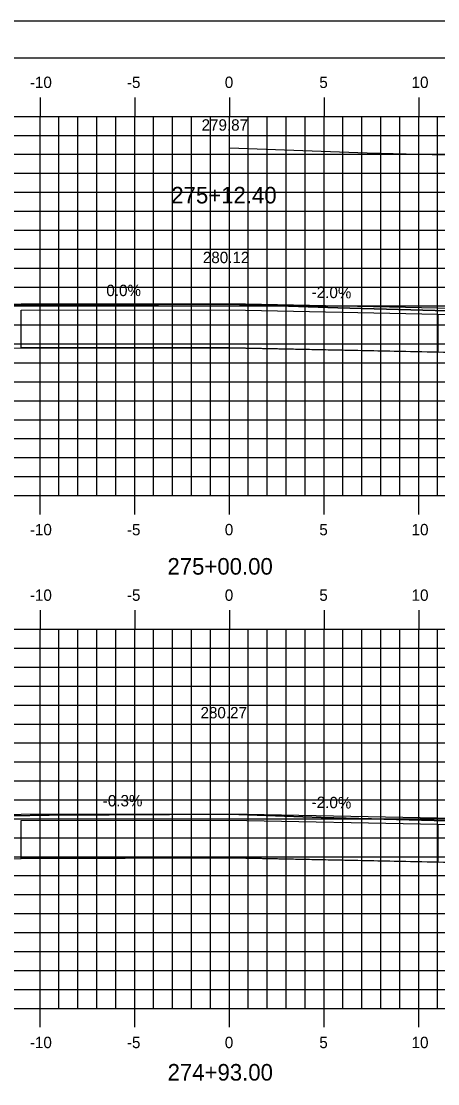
# Model space of a CAD drawing. Extents: x 853340 to 853510, y 366268 to 366378.
# Drawn here: x 853412.1 to 853434.1, y 366322.1 to 366378.2 of the extents above; entities that cross this region are included whole.
import ezdxf

# ---------------------------------------------------------------- set-up
doc = ezdxf.new("R2010")
doc.units = 0
for name, color, linetype in [('ANNOTATION', 7, 'Continuous'), ('BORDER', 7, 'Continuous'), ('D_Roadway_Centerline_Text', 7, 'Continuous'), ('D_Roadway_Edge_TW', 7, 'Continuous'), ('D_Roadway_SubGrade', 7, 'Continuous'), ('H_V ANNOTATION', 7, 'Continuous'), ('JUNK COM EXC', 7, 'Continuous'), ('MAJOR', 7, 'Continuous'), ('MINOR', 7, 'Continuous'), ('PLOT BOUNDARY', 7, 'Continuous'), ('S_Roadway_Centerline', 7, 'Continuous')]:
    doc.layers.add(name, color=color, linetype=linetype)

msp = doc.modelspace()

# ---------------------------------------------------------------- linework, layer by layer
at = {"layer": 'BORDER'}
msp.add_line((853508.1, 366376.236), (853348.1, 366376.236), dxfattribs=at)
at = {"layer": 'D_Roadway_Edge_TW'}
for points in [[(853404.1, 366362.952), (853412.1, 366363.272), (853423.1, 366363.28), (853434.1, 366363.06), (853442.1, 366362.74)], [(853404.1, 366336.023), (853412.1, 366336.343), (853423.1, 366336.366), (853434.1, 366336.146), (853442.099, 366335.825)]]:
    msp.add_lwpolyline(points, dxfattribs=at)
at = {"layer": 'D_Roadway_SubGrade'}
for points in [[(853412.107, 366360.939), (853412.107, 366362.939), (853423.107, 366362.947), (853434.107, 366362.727), (853434.107, 366360.727), (853423.107, 366360.947)], [(853412.107, 366334.01), (853412.107, 366336.01), (853423.107, 366336.033), (853434.107, 366335.813), (853434.107, 366333.813), (853423.107, 366334.033)]]:
    msp.add_lwpolyline(points, close=True, dxfattribs=at)
for points in [[(853442.107, 366360.567), (853434.107, 366360.727), (853434.107, 366362.727), (853442.107, 366362.407), (853442.107, 366360.567)], [(853442.1, 366333.653), (853434.107, 366333.813), (853434.107, 366335.813), (853442.1, 366335.493)]]:
    msp.add_lwpolyline(points, dxfattribs=at)
at = {"layer": 'JUNK COM EXC'}
for points in [[(853403.1, 366362.838), (853403.1, 366360.759), (853412.107, 366360.939), (853423.107, 366360.947), (853443.101, 366360.548), (853443.1, 366362.612), (853435.895, 366362.863), (853428.824, 366363.051), (853423.1, 366363.253), (853411.854, 366363.201), (853411.562, 366363.195), (853404.759, 366362.908), (853404.544, 366362.894), (853403.28, 366362.845), (853403.1, 366362.838)], [(853403.1, 366335.883), (853403.1, 366333.83), (853412.107, 366334.01), (853423.107, 366334.033), (853443.1, 366333.633), (853443.1, 366335.711), (853435.908, 366335.962), (853427.945, 366336.173), (853423.1, 366336.344), (853413.581, 366336.299), (853411.556, 366336.262), (853405.802, 366336.019), (853404.553, 366335.94), (853403.1, 366335.883)]]:
    msp.add_lwpolyline(points, dxfattribs=at)
at = {"layer": 'MAJOR'}
for p, q in [((853413.1, 366374.158), (853413.1, 366373.156)), ((853418.1, 366374.158), (853418.1, 366373.156)), ((853423.1, 366374.158), (853423.1, 366373.156)), ((853428.1, 366374.158), (853428.1, 366373.156)), ((853433.1, 366374.158), (853433.1, 366373.156)), ((853353.1, 366373.156), (853493.1, 366373.156)), ((853353.1, 366373.156), (853493.1, 366373.156)), ((853413.1, 366353.156), (853413.1, 366373.156)), ((853418.1, 366353.156), (853418.1, 366373.156)), ((853423.1, 366353.156), (853423.1, 366373.156)), ((853428.1, 366353.156), (853428.1, 366373.156)), ((853433.1, 366353.156), (853433.1, 366373.156)), ((853353.1, 366368.156), (853493.1, 366368.156)), ((853353.1, 366363.156), (853493.1, 366363.156)), ((853353.1, 366358.156), (853493.1, 366358.156)), ((853353.1, 366353.156), (853493.1, 366353.156)), ((853353.1, 366353.156), (853493.1, 366353.156)), ((853413.1, 366352.154), (853413.1, 366353.156)), ((853418.1, 366352.154), (853418.1, 366353.156)), ((853423.1, 366352.154), (853423.1, 366353.156)), ((853428.1, 366352.154), (853428.1, 366353.156)), ((853433.1, 366352.154), (853433.1, 366353.156)), ((853413.1, 366347.101), (853413.1, 366346.099)), ((853418.1, 366347.101), (853418.1, 366346.099)), ((853423.1, 366347.101), (853423.1, 366346.099)), ((853428.1, 366347.101), (853428.1, 366346.099)), ((853433.1, 366347.101), (853433.1, 366346.099)), ((853353.1, 366346.099), (853493.1, 366346.099)), ((853353.1, 366346.099), (853493.1, 366346.099)), ((853413.1, 366326.099), (853413.1, 366346.099)), ((853418.1, 366326.099), (853418.1, 366346.099)), ((853423.1, 366326.099), (853423.1, 366346.099)), ((853428.1, 366326.099), (853428.1, 366346.099)), ((853433.1, 366326.099), (853433.1, 366346.099)), ((853353.1, 366341.099), (853493.1, 366341.099)), ((853353.1, 366336.099), (853493.1, 366336.099)), ((853353.1, 366331.099), (853493.1, 366331.099)), ((853353.1, 366326.099), (853493.1, 366326.099)), ((853353.1, 366326.099), (853493.1, 366326.099)), ((853413.1, 366325.097), (853413.1, 366326.099)), ((853418.1, 366325.097), (853418.1, 366326.099)), ((853423.1, 366325.097), (853423.1, 366326.099)), ((853428.1, 366325.097), (853428.1, 366326.099)), ((853433.1, 366325.097), (853433.1, 366326.099))]:
    msp.add_line(p, q, dxfattribs=at)
at = {"layer": 'MINOR'}
for p, q in [((853414.1, 366353.156), (853414.1, 366373.156)), ((853415.1, 366353.156), (853415.1, 366373.156)), ((853416.1, 366353.156), (853416.1, 366373.156)), ((853417.1, 366353.156), (853417.1, 366373.156)), ((853419.1, 366353.156), (853419.1, 366373.156)), ((853420.1, 366353.156), (853420.1, 366373.156)), ((853421.1, 366353.156), (853421.1, 366373.156)), ((853422.1, 366353.156), (853422.1, 366373.156)), ((853424.1, 366353.156), (853424.1, 366373.156)), ((853425.1, 366353.156), (853425.1, 366373.156)), ((853426.1, 366353.156), (853426.1, 366373.156)), ((853427.1, 366353.156), (853427.1, 366373.156)), ((853429.1, 366353.156), (853429.1, 366373.156)), ((853430.1, 366353.156), (853430.1, 366373.156)), ((853431.1, 366353.156), (853431.1, 366373.156)), ((853432.1, 366353.156), (853432.1, 366373.156)), ((853434.1, 366353.156), (853434.1, 366373.156)), ((853353.1, 366372.156), (853493.1, 366372.156)), ((853353.1, 366371.156), (853493.1, 366371.156)), ((853353.1, 366370.156), (853493.1, 366370.156)), ((853353.1, 366369.156), (853493.1, 366369.156)), ((853353.1, 366367.156), (853493.1, 366367.156)), ((853353.1, 366366.156), (853493.1, 366366.156)), ((853353.1, 366365.156), (853493.1, 366365.156)), ((853353.1, 366364.156), (853493.1, 366364.156)), ((853353.1, 366362.156), (853493.1, 366362.156)), ((853353.1, 366361.156), (853493.1, 366361.156)), ((853353.1, 366360.156), (853493.1, 366360.156)), ((853353.1, 366359.156), (853493.1, 366359.156)), ((853353.1, 366357.156), (853493.1, 366357.156)), ((853353.1, 366356.156), (853493.1, 366356.156)), ((853353.1, 366355.156), (853493.1, 366355.156)), ((853353.1, 366354.156), (853493.1, 366354.156)), ((853414.1, 366326.099), (853414.1, 366346.099)), ((853415.1, 366326.099), (853415.1, 366346.099)), ((853416.1, 366326.099), (853416.1, 366346.099)), ((853417.1, 366326.099), (853417.1, 366346.099)), ((853419.1, 366326.099), (853419.1, 366346.099)), ((853420.1, 366326.099), (853420.1, 366346.099)), ((853421.1, 366326.099), (853421.1, 366346.099)), ((853422.1, 366326.099), (853422.1, 366346.099)), ((853424.1, 366326.099), (853424.1, 366346.099)), ((853425.1, 366326.099), (853425.1, 366346.099)), ((853426.1, 366326.099), (853426.1, 366346.099)), ((853427.1, 366326.099), (853427.1, 366346.099)), ((853429.1, 366326.099), (853429.1, 366346.099)), ((853430.1, 366326.099), (853430.1, 366346.099)), ((853431.1, 366326.099), (853431.1, 366346.099)), ((853432.1, 366326.099), (853432.1, 366346.099)), ((853434.1, 366326.099), (853434.1, 366346.099)), ((853353.1, 366345.099), (853493.1, 366345.099)), ((853353.1, 366344.099), (853493.1, 366344.099)), ((853353.1, 366343.099), (853493.1, 366343.099)), ((853353.1, 366342.099), (853493.1, 366342.099)), ((853353.1, 366340.099), (853493.1, 366340.099)), ((853353.1, 366339.099), (853493.1, 366339.099)), ((853353.1, 366338.099), (853493.1, 366338.099)), ((853353.1, 366337.099), (853493.1, 366337.099)), ((853353.1, 366335.099), (853493.1, 366335.099)), ((853353.1, 366334.099), (853493.1, 366334.099)), ((853353.1, 366333.099), (853493.1, 366333.099)), ((853353.1, 366332.099), (853493.1, 366332.099)), ((853353.1, 366330.099), (853493.1, 366330.099)), ((853353.1, 366329.099), (853493.1, 366329.099)), ((853353.1, 366328.099), (853493.1, 366328.099)), ((853353.1, 366327.099), (853493.1, 366327.099))]:
    msp.add_line(p, q, dxfattribs=at)
at = {"layer": 'PLOT BOUNDARY'}
msp.add_lwpolyline([(853340.007, 366268.177), (853510.007, 366268.177), (853510.007, 366378.177), (853340.007, 366378.177)], close=True, dxfattribs=at)
at = {"layer": 'S_Roadway_Centerline'}
for points in [[(853423.1, 366371.492), (853430.382, 366371.235), (853435.872, 366371.089), (853446.468, 366370.72), (853448.861, 366370.64), (853449.231, 366371.012), (853449.329, 366371.104), (853449.384, 366371.065), (853449.544, 366370.995), (853458.624, 366371.375), (853461.455, 366371.527), (853464.215, 366371.694), (853468.073, 366371.793)], [(853379.745, 366362.132), (853396.858, 366362.243), (853400.236, 366362.728), (853403.28, 366362.845), (853404.544, 366362.894), (853404.759, 366362.908), (853411.562, 366363.195), (853411.854, 366363.201), (853423.1, 366363.253), (853428.824, 366363.051), (853435.895, 366362.863), (853448.102, 366362.438), (853448.825, 366362.419), (853451.873, 366362.862), (853452.264, 366362.884), (853453.558, 366362.897), (853453.702, 366362.932), (853455.448, 366363.065), (853466.573, 366363.351)], [(853397.921, 366335.625), (853399.647, 366335.648), (853400.667, 366335.788), (853404.553, 366335.94), (853405.802, 366336.019), (853411.556, 366336.262), (853413.581, 366336.299), (853423.1, 366336.344), (853427.945, 366336.173), (853435.908, 366335.962), (853446.195, 366335.603), (853448.746, 366335.536), (853449.861, 366335.698), (853453.832, 366335.929), (853466.982, 366336.058), (853467.693, 366336.23)]]:
    msp.add_lwpolyline(points, dxfattribs=at)

# ---------------------------------------------------------------- texts
at = {"layer": 'ANNOTATION'}
for s, rotation, p in [('0.0%', 0.0401, (853416.604, 366363.675)), ('-2.0%', 358.8542, (853427.443, 366363.593)), ('-0.3%', 0.1175, (853416.415, 366336.752)), ('-2.0%', 358.8542, (853427.443, 366336.679))]:
    msp.add_text(s, height=0.6, rotation=rotation, dxfattribs=at).set_placement(p)
at = {"layer": 'D_Roadway_Centerline_Text'}
for s, p in [('279.87', (853421.633, 366372.405)), ('280.12', (853421.7, 366365.415)), ('280.27', (853421.575, 366341.398))]:
    msp.add_text(s, height=0.6, dxfattribs=at).set_placement(p)
at = {"layer": 'H_V ANNOTATION'}
for s, height, p in [('-10', 0.6, (853412.565, 366374.656)), ('-5', 0.6, (853417.69, 366374.656)), ('0', 0.6, (853422.859, 366374.656)), ('5', 0.6, (853427.851, 366374.656)), ('10', 0.6, (853432.725, 366374.656)), ('275+12.40', 0.875, (853420.033, 366368.565)), ('-10', 0.6, (853412.565, 366351.056)), ('-5', 0.6, (853417.69, 366351.056)), ('0', 0.6, (853422.859, 366351.056)), ('5', 0.6, (853427.851, 366351.056)), ('10', 0.6, (853432.725, 366351.056)), ('275+00.00', 0.875, (853419.83, 366348.981)), ('-10', 0.6, (853412.565, 366347.599)), ('-5', 0.6, (853417.69, 366347.599)), ('0', 0.6, (853422.859, 366347.599)), ('5', 0.6, (853427.851, 366347.599)), ('10', 0.6, (853432.725, 366347.599)), ('-10', 0.6, (853412.565, 366323.999)), ('-5', 0.6, (853417.69, 366323.999)), ('0', 0.6, (853422.859, 366323.999)), ('5', 0.6, (853427.851, 366323.999)), ('10', 0.6, (853432.725, 366323.999)), ('274+93.00', 0.875, (853419.838, 366322.287))]:
    msp.add_text(s, height=height, dxfattribs=at).set_placement(p)
at = {"layer": 'S_Roadway_Centerline'}
for s, p in [('C', (853423.095, 366363.253)), ('L', (853423.1, 366363.245)), ('C', (853423.095, 366336.344)), ('L', (853423.1, 366336.336))]:
    msp.add_text(s, height=0.0146, dxfattribs=at).set_placement(p)

doc.saveas('drawing.dxf')
